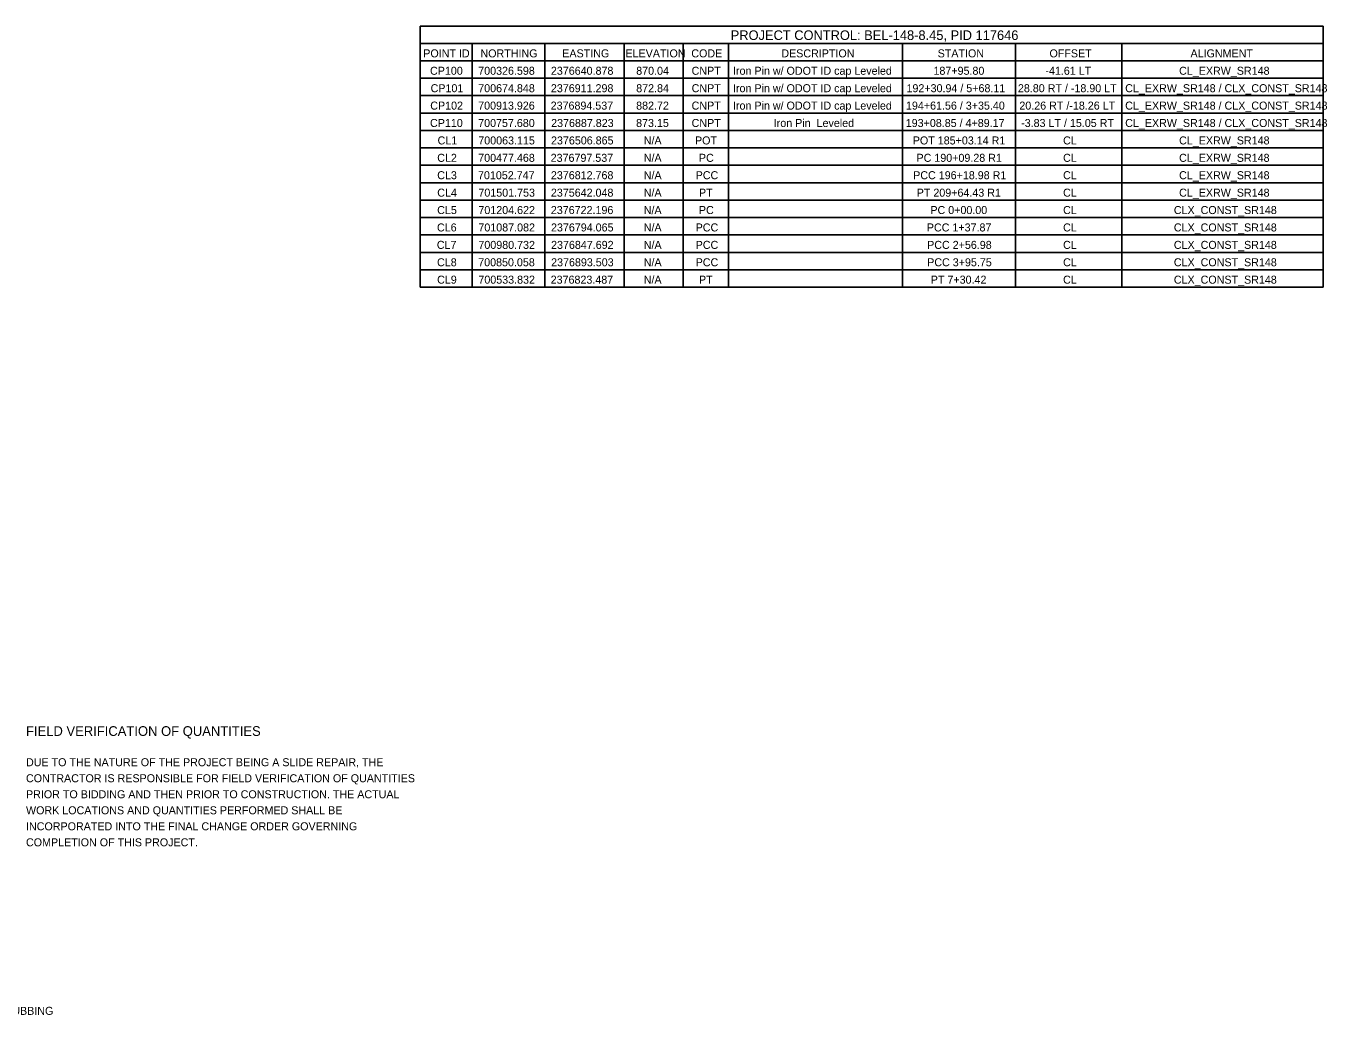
# Model space of a CAD drawing. Extents: x -286 to 93, y -30 to 99.
# Drawn here: x 17.24 to 39.99, y 25.75 to 43.03 of the extents above; entities that cross this region are included whole.
import ezdxf

# ---------------------------------------------------------------- set-up
doc = ezdxf.new("R2010")
doc.units = 0
doc.layers.add('SH_Text', color=7, linetype='Continuous')

msp = doc.modelspace()

# ---------------------------------------------------------------- linework, layer by layer
at = {"layer": 'SH_Text'}
for p, q in [((24.132, 43.034), (39.924, 43.034)), ((24.132, 43.034), (24.132, 38.469)), ((39.924, 43.034), (39.924, 38.469)), ((24.132, 42.73), (39.924, 42.73)), ((25.045, 42.73), (25.045, 42.425)), ((26.313, 42.73), (26.313, 42.425)), ((27.699, 42.73), (27.699, 42.425)), ((28.731, 42.73), (28.731, 42.425)), ((29.525, 42.73), (29.525, 42.425)), ((32.569, 42.73), (32.569, 42.425)), ((34.547, 42.73), (34.547, 42.425)), ((36.407, 42.73), (36.407, 42.425)), ((24.132, 42.425), (39.924, 42.425)), ((25.045, 42.425), (25.045, 38.469)), ((26.313, 42.425), (26.313, 38.469)), ((27.699, 42.425), (27.699, 38.469)), ((28.731, 42.425), (28.731, 38.469)), ((29.525, 42.425), (29.525, 38.469)), ((32.569, 42.425), (32.569, 38.469)), ((34.547, 42.425), (34.547, 38.469)), ((36.407, 42.425), (36.407, 38.469)), ((24.132, 42.121), (39.924, 42.121)), ((24.132, 41.817), (39.924, 41.817)), ((24.132, 41.512), (39.924, 41.512)), ((24.132, 41.208), (39.924, 41.208)), ((24.132, 40.904), (39.924, 40.904)), ((24.132, 40.599), (39.924, 40.599)), ((24.132, 40.295), (39.924, 40.295)), ((24.132, 39.99), (39.924, 39.99)), ((24.132, 39.686), (39.924, 39.686)), ((24.132, 39.382), (39.924, 39.382)), ((24.132, 39.077), (39.924, 39.077)), ((24.132, 38.773), (39.924, 38.773)), ((24.132, 38.469), (39.924, 38.469))]:
    msp.add_line(p, q, dxfattribs=at)

# ---------------------------------------------------------------- texts
for s, height, p in [('PROJECT CONTROL: BEL-148-8.45, PID 117646', 0.168, (29.565, 42.79)), ('POINT ID', 0.14, (24.188, 42.486)), ('NORTHING', 0.14, (25.188, 42.486)), ('EASTING', 0.14, (26.619, 42.486)), ('ELEVATION', 0.14, (27.724, 42.486)), ('CODE', 0.14, (28.876, 42.486)), ('DESCRIPTION', 0.14, (30.45, 42.486)), ('STATION', 0.14, (33.184, 42.486)), ('OFFSET', 0.14, (35.14, 42.486)), ('ALIGNMENT', 0.14, (37.606, 42.486)), ('CP100', 0.14, (24.306, 42.182)), ('700326.598', 0.14, (25.149, 42.182)), ('2376640.878', 0.14, (26.42, 42.182)), ('870.04', 0.14, (27.912, 42.182)), ('CNPT', 0.14, (28.881, 42.182)), ('Iron Pin w/ ODOT ID cap Leveled', 0.14, (29.605, 42.182)), (' 187+95.80', 0.14, (33.059, 42.182)), ('-41.61 LT', 0.14, (35.068, 42.182)), ('CL_EXRW_SR148', 0.14, (37.407, 42.182)), ('CP101', 0.14, (24.316, 41.877)), ('700674.848', 0.14, (25.149, 41.877)), ('2376911.298', 0.14, (26.42, 41.877)), ('872.84', 0.14, (27.912, 41.877)), ('CNPT', 0.14, (28.881, 41.877)), ('Iron Pin w/ ODOT ID cap Leveled', 0.14, (29.605, 41.877)), ('192+30.94 / 5+68.11', 0.14, (32.639, 41.877)), ('28.80 RT / -18.90 LT', 0.14, (34.588, 41.877)), ('CL_EXRW_SR148 / CLX_CONST_SR148', 0.14, (36.464, 41.877)), ('CP102', 0.14, (24.31, 41.573)), ('700913.926', 0.14, (25.148, 41.573)), ('2376894.537', 0.14, (26.416, 41.573)), ('882.72', 0.14, (27.911, 41.573)), ('CNPT', 0.14, (28.881, 41.573)), ('Iron Pin w/ ODOT ID cap Leveled', 0.14, (29.605, 41.573)), ('194+61.56 / 3+35.40', 0.14, (32.63, 41.573)), ('20.26 RT /-18.26 LT', 0.14, (34.613, 41.573)), ('CL_EXRW_SR148 / CLX_CONST_SR148', 0.14, (36.464, 41.573)), ('CP110', 0.14, (24.306, 41.269)), ('700757.680', 0.14, (25.148, 41.269)), ('2376887.823', 0.14, (26.424, 41.269)), ('873.15', 0.14, (27.91, 41.269)), ('CNPT', 0.14, (28.881, 41.269)), ('Iron Pin  Leveled', 0.14, (30.318, 41.269)), ('193+08.85 / 4+89.17', 0.14, (32.626, 41.269)), ('-3.83 LT / 15.05 RT', 0.14, (34.644, 41.269)), ('CL_EXRW_SR148 / CLX_CONST_SR148', 0.14, (36.464, 41.269)), ('CL1', 0.14, (24.438, 40.964)), ('700063.115', 0.14, (25.15, 40.964)), ('2376506.865', 0.14, (26.422, 40.964)), ('N/A', 0.14, (28.044, 40.964)), ('POT', 0.14, (28.94, 40.964)), ('POT 185+03.14 R1', 0.14, (32.749, 40.964)), ('CL', 0.14, (35.378, 40.964)), ('CL_EXRW_SR148', 0.14, (37.407, 40.964)), ('CL2', 0.14, (24.432, 40.66)), ('700477.468', 0.14, (25.149, 40.66)), ('2376797.537', 0.14, (26.416, 40.66)), ('N/A', 0.14, (28.044, 40.66)), ('PC', 0.14, (29.009, 40.66)), ('PC 190+09.28 R1', 0.14, (32.814, 40.66)), ('CL', 0.14, (35.378, 40.66)), ('CL_EXRW_SR148', 0.14, (37.407, 40.66)), ('N/A', 0.14, (28.044, 40.356)), ('CL3', 0.14, (24.432, 40.356)), ('701052.747', 0.14, (25.145, 40.356)), ('2376812.768', 0.14, (26.42, 40.356)), ('PCC', 0.14, (28.952, 40.356)), ('PCC 196+18.98 R1', 0.14, (32.756, 40.356)), ('CL', 0.14, (35.378, 40.356)), ('CL_EXRW_SR148', 0.14, (37.407, 40.356)), ('CL4', 0.14, (24.432, 40.051)), ('701501.753', 0.14, (25.152, 40.051)), ('2375642.048', 0.14, (26.42, 40.051)), ('N/A', 0.14, (28.044, 40.051)), ('PT', 0.14, (29.01, 40.051)), ('PT 209+64.43 R1', 0.14, (32.818, 40.051)), ('CL', 0.14, (35.378, 40.051)), ('CL_EXRW_SR148', 0.14, (37.407, 40.051)), ('CL5', 0.14, (24.431, 39.747)), ('701204.622', 0.14, (25.152, 39.747)), ('2376722.196', 0.14, (26.419, 39.747)), ('N/A', 0.14, (28.044, 39.747)), ('PC', 0.14, (29.009, 39.747)), ('PC 0+00.00', 0.14, (33.057, 39.747)), ('CL', 0.14, (35.378, 39.747)), ('CLX_CONST_SR148', 0.14, (37.315, 39.747)), ('CL6', 0.14, (24.428, 39.443)), ('701087.082', 0.14, (25.152, 39.443)), ('2376794.065', 0.14, (26.422, 39.443)), ('N/A', 0.14, (28.044, 39.443)), ('PCC', 0.14, (28.952, 39.443)), ('PCC 1+37.87', 0.14, (32.995, 39.443)), ('CL', 0.14, (35.378, 39.443)), ('CLX_CONST_SR148', 0.14, (37.315, 39.443)), ('CL7', 0.14, (24.425, 39.138)), ('700980.732', 0.14, (25.152, 39.138)), ('2376847.692', 0.14, (26.423, 39.138)), ('N/A', 0.14, (28.044, 39.138)), ('PCC', 0.14, (28.952, 39.138)), ('PCC 2+56.98', 0.14, (33, 39.138)), ('CL', 0.14, (35.378, 39.138)), ('CLX_CONST_SR148', 0.14, (37.315, 39.138)), ('CL8', 0.14, (24.429, 38.834)), ('700850.058', 0.14, (25.149, 38.834)), ('2376893.503', 0.14, (26.424, 38.834)), ('N/A', 0.14, (28.044, 38.834)), ('PCC', 0.14, (28.952, 38.834)), ('PCC 3+95.75', 0.14, (33.001, 38.834)), ('CL', 0.14, (35.378, 38.834)), ('CLX_CONST_SR148', 0.14, (37.315, 38.834)), ('CL9', 0.14, (24.43, 38.53)), ('700533.832', 0.14, (25.152, 38.53)), ('2376823.487', 0.14, (26.416, 38.53)), ('N/A', 0.14, (28.044, 38.53)), ('PT', 0.14, (29.01, 38.53)), ('PT 7+30.42', 0.14, (33.064, 38.53)), ('CL', 0.14, (35.378, 38.53)), ('CLX_CONST_SR148', 0.14, (37.315, 38.53)), ('FIELD VERIFICATION OF QUANTITIES', 0.17, (17.24, 30.624)), ('DUE TO THE NATURE OF THE PROJECT BEING A SLIDE REPAIR, THE ', 0.14, (17.24, 30.094)), ('CONTRACTOR IS RESPONSIBLE FOR FIELD VERIFICATION OF QUANTITIES ', 0.14, (17.24, 29.814)), ('PRIOR TO BIDDING AND THEN PRIOR TO CONSTRUCTION. THE ACTUAL ', 0.14, (17.24, 29.534)), ('WORK LOCATIONS AND QUANTITIES PERFORMED SHALL BE ', 0.14, (17.24, 29.254)), ('INCORPORATED INTO THE FINAL CHANGE ORDER GOVERNING ', 0.14, (17.24, 28.974)), ('COMPLETION OF THIS PROJECT.', 0.14, (17.24, 28.694)), ('CLEARING AND GRUBBING', 0.14, (15.263, 25.748))]:
    msp.add_text(s, height=height, dxfattribs=at).set_placement(p)

doc.saveas('drawing.dxf')
